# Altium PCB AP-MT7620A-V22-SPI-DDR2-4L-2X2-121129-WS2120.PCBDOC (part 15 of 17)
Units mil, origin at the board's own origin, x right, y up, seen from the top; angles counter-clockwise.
Board outline 7316 x 4279 mil, 4 copper layers (Top, Inner Layer 2, Inner Layer 3, Bottom), stack 35.4 mil thick; 640 components, 473 nets, 2041 pads, 2358 vias.
Unrouted connection lines stored in the file: 11.
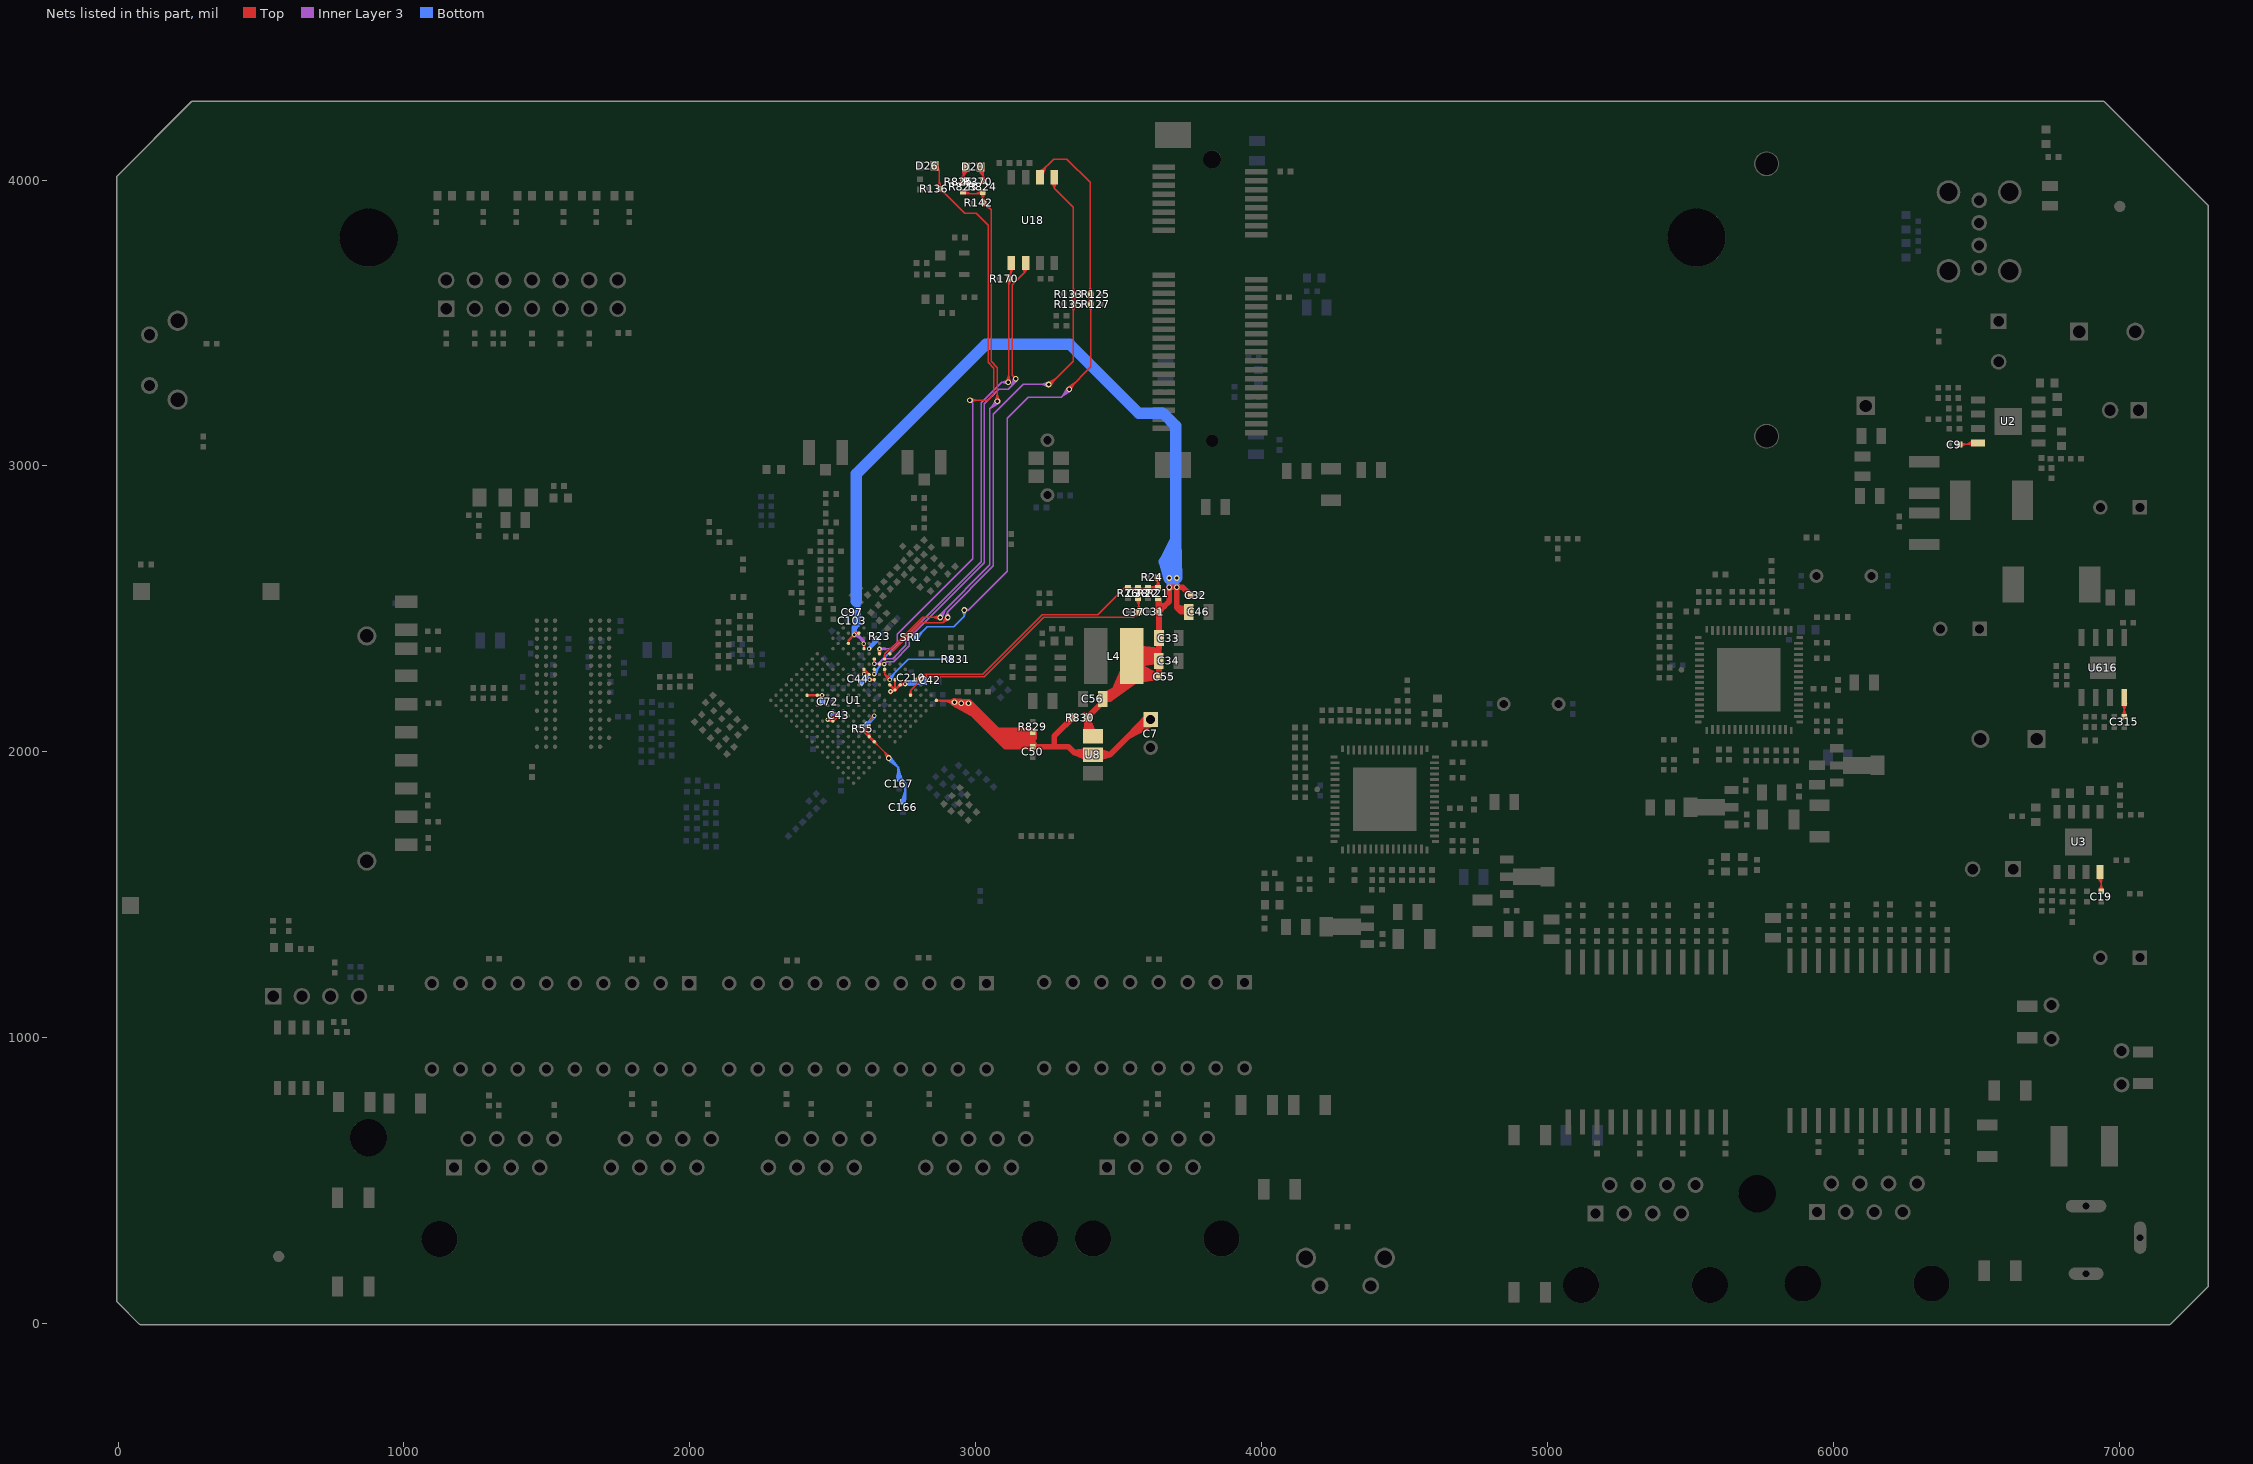
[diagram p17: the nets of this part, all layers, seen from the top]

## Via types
v1: diameter 20, hole 12, Top to Bottom, 2117 vias
v2: diameter 16, hole 8, Top to Bottom, 241 vias

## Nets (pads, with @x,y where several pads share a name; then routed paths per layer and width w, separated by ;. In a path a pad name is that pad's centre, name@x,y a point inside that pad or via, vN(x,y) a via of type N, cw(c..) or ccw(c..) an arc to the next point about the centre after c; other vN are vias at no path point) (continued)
SECLED_6-LED1: D20.1 R370.1 R824.2 | length 1100.5
  Top w4: R824.2@3025,3994 3026,3994 R370.1@3027,3994
  Top w4.5: D20.1@3006.28,4038.36 3026,4014.57 ; D20.1@3009.99,4041 3026,4014.57 ; D20.1@3014.01,4043.05 3026,4014.57 ; D20.1@3016.59,4044 3026,4014.57 ; D20.1@3016.59,4046 3022.59,4040 3026,4040 R370.1@3026,3994 ; R370.1@3017.42,3995.6 3026,4017.53 ; D20.1@3019.25,4044.72 3026,4014.57 ; R370.1@3021.77,3994.36 3026,4017.53 ; D20.1@3023.71,4045.38 3026,4014.57 ; R824.2@3025,3994 3026,4017.53 ; R370.1@3028.25,3994.09 3026,4017.53 ; D20.1@3028.26,4045.38 3026,4014.57 ; R370.1@3032.69,3994.95 3026,4017.53 ; R370.1@3019.31,3994.95 3026,4017.53 ; R370.1@3019.31,3994.95 3026,4017.53 ; R370.1@3019.31,3994.95 3026,4017.53 ; R370.1@3019.31,3994.95 3026,4017.53 ; R370.1@3019.31,3994.95 3026,4017.53 ; R370.1@3019.31,3994.95 3026,4017.53 ; R370.1@3023.75,3994.09 3026,4017.53 ; R370.1@3023.75,3994.09 3026,4017.53 ; R370.1@3023.75,3994.09 3026,4017.53 ; R370.1@3023.75,3994.09 3026,4017.53 ; R370.1@3023.75,3994.09 3026,4017.53 ; R370.1@3023.75,3994.09 3026,4017.53 ; 3026,4017.53 R370.1@3034.58,3995.6 ; 3026,4017.53 R370.1@3030.23,3994.36 ; 3026,4017.53 R370.1@3027,3994 ; 3026,4017.53 R370.1@3034.58,3995.6 ; 3026,4017.53 R370.1@3030.23,3994.36 ; 3026,4017.53 R370.1@3027,3994 ; 3026,4017.53 R370.1@3034.58,3995.6 ; 3026,4017.53 R370.1@3030.23,3994.36 ; 3026,4017.53 R370.1@3027,3994 ; 3026,4017.53 R370.1@3034.58,3995.6 ; 3026,4017.53 R370.1@3030.23,3994.36 ; 3026,4017.53 R370.1@3027,3994 ; 3026,4017.53 R370.1@3034.58,3995.6 ; 3026,4017.53 R370.1@3030.23,3994.36 ; 3026,4017.53 R370.1@3027,3994 ; 3026,4017.53 R370.1@3034.58,3995.6 ; 3026,4017.53 R370.1@3030.23,3994.36 ; 3026,4017.53 R370.1@3027,3994
SECU_LED_6-LED1: D20.2 R823.2 R825.1 | length 1077
  Top w4: R823.2@2956,3995 R825.1@2958,3995
  Top w4.5: R823.2@2948.36,3996.28 2956,4018.5 ; R823.2@2950.27,3995.62 2956,4018.63 ; D20.2@2953.75,4045.42 2956,4015.25 ; R823.2@2954.75,3994.95 2956,4018.63 ; R825.1@2958,3995 2956,4018.63 ; D20.2@2958.3,4045.41 2956,4015.25 ; R823.2@2961.21,3995.5 2956,4018.63 ; D20.2@2962.76,4044.74 2956,4015.25 ; D20.2@2965.41,4044 2956,4015.25 ; D20.2@2965.41,4046 2956,4046 R823.2@2956,3995 ; R823.2@2965.51,3996.91 2956,4018.63 ; D20.2@2967.98,4043.03 2956,4015.25 ; D20.2@2971.98,4040.94 2956,4015.25 ; D20.2@2975.65,4038.25 2956,4015.25 ; R823.2@2948.35,3996.27 2956,4018.63 ; R823.2@2948.35,3996.27 2956,4018.63 ; R823.2@2948.36,3996.27 2956,4018.54 ; R823.2@2948.35,3996.27 2956,4018.63 ; R823.2@2948.35,3996.27 2956,4018.61 ; R823.2@2952.76,3995.22 2956,4018.63 ; R823.2@2952.76,3995.22 2956,4018.63 ; R823.2@2952.76,3995.22 2956,4018.54 ; R823.2@2952.76,3995.22 2956,4018.63 ; R823.2@2952.76,3995.22 2956,4018.61 ; R823.2@2952.76,3995.22 2956,4018.5 ; R823.2@2956,3995 2956,4018.63 ; R823.2@2956,3995 2956,4018.63 ; R823.2@2956,3995 2956,4018.54 ; R823.2@2956,3995 2956,4018.63 ; R823.2@2956,3995 2956,4018.61 ; 2956,4018.5 2963.64,3996.28 2956,4018.54 ; 2956,4018.5 R823.2@2959.24,3995.22 ; 2956,4018.54 R823.2@2959.24,3995.23 ; 2956,4018.61 R823.2@2963.65,3996.27 ; 2956,4018.61 R823.2@2959.24,3995.22 ; 2956,4018.63 R823.2@2963.65,3996.27 ; 2956,4018.63 R823.2@2959.24,3995.22 ; 2956,4018.63 R823.2@2963.65,3996.27 ; 2956,4018.63 R823.2@2959.24,3995.22 ; 2956,4018.63 R823.2@2963.65,3996.27 ; 2956,4018.63 R823.2@2959.24,3995.22
SFLASH_CLK_1-CPU-RT0: SR1.1 U1.D8 | length 383.6
  Top w8: v2(2645.2,2272) U1.D8@2645.38,2288.57 v2(2645.2,2272)
  Bottom w5: v2@2640.91,2275.45 2660.89,2295.89 ; v2@2650.07,2269.44 2660.89,2295.89 ; SR1.1@2750.61,2405.21 2733.05,2381.67 ; SR1.1@2759.89,2393.59 2733.05,2381.67 ; 2660.89,2295.89 v2(2645.2,2272) 2645.2,2280.2 2664,2299 2664,2312.62 2751.38,2400 SR1.1@2756,2400 2733.05,2381.67
SOC_1.2VD: C7.1 C42.1 C43.1 C44.1 C50.1 C72.1 C166.1 C167.1 C210.1 R23.1 R55.1 R829.1 R830.1 U1.A17 U1.C11 U1.C12 U1.D11 U1.D12 U1.E7 U1.E8 U1.E9 U1.K13 U1.L13 U1.L14 U1.L15 U1.M5 U1.M9 U1.N4 U1.N9 U8.2 | length 9993
  Top w4: U1.L14@2624.84,2050.29 2639.95,2040.67 ; U1.K13@2627.29,2089.52 U1.K13@2628,2090.24 ; U1.L14@2630.33,2055.78 2639.95,2040.67 ; 2631,2110.47 2631,2111.17 ; v2@2640.44,2129.32 2631,2111.17 ; U1.L15@2642.05,2033.19 2634.28,2049.58 ; U1.L15@2642.67,2032.42 2630.98,2046.38 ; U1.L15@2642.94,2032.19 2658.04,2022.58 U1.L15@2648.43,2037.68 ; U1.L15@2647.43,2038.57 2630.98,2046.38 ; U1.L15@2648.19,2037.95 2634.28,2049.58 ; v2@2648.93,2121.02 2631,2111.17 ; v1@2689.05,1974.42 2679.05,2001.57 ; v1@2692.71,1976.07 2679.05,2001.57 ; U1.D11@2697.22,2231.24 2712.33,2221.62 ; v1@2699.16,1980.78 2679.05,2001.57 ; v1@2701.85,1983.76 2679.05,2001.57 ; U1.D11@2702.71,2236.73 2712.33,2221.62 ; U1.D12@2714.43,2214.15 2706.66,2230.53 ; U1.D12@2714.95,2218.9 2728.88,2230.55 ; U1.D12@2715.05,2213.38 2703.37,2227.33 ; U1.D12@2715.72,2219.52 2732.12,2227.31 ; U1.D12@2719.81,2219.52 2703.37,2227.33 ; U1.D12@2720.47,2213.38 2732.12,2227.31 ; U1.D12@2720.57,2218.9 2706.66,2230.53 ; U1.D12@2721.09,2214.15 2728.88,2230.55 ; U1.C12@2732.81,2236.73 2723.2,2221.62 ; U1.C12@2734.56,2237.97 2741,2238.17 ; U1.C12@2738.3,2231.24 2723.2,2221.62 ; U1.C12@2739.05,2232.03 2741,2238.17 ; U1.A17@2862.52,2180 U1.A17@2866,2180 ; 2630.98,2046.38 U1.L15@2645.38,2035.24 ; 2631,2111.17 2643.83,2124 2643.83,2124.33 v2(2645.3,2125.8) 2631,2111.17 ; 2632.72,2047.9 2642.33,2032.79 2632.72,2047.9 ; 2632.72,2047.9 2647.83,2038.28 2632.72,2047.9 ; 2634.28,2049.58 U1.L15@2645.38,2035.24 ; 2639.95,2040.67 U1.L14@2627.29,2053.33 U1.L15@2645.38,2035.24 ; 2639.95,2040.67 U1.L15@2642.01,2033.27 ; 2639.95,2040.67 U1.L15@2647.35,2038.61 ; 2639.95,2040.67 U1.L15@2645.38,2035.24 ; 2639.95,2040.67 U1.L15@2642.01,2033.27 ; 2639.95,2040.67 U1.L15@2647.35,2038.61 ; 2639.95,2040.67 U1.L15@2642.01,2033.27 ; 2639.95,2040.67 U1.L15@2647.35,2038.61 ; 2639.95,2040.67 U1.L15@2645.38,2035.24 ; U1.L15@2645.38,2035.24 2695.8,1984.82 v1(2696.1,1978.2) 2679.05,2001.57 ; 2703.37,2227.33 U1.D12@2717.76,2216.19 ; 2705.1,2228.85 2714.72,2213.75 2705.1,2228.85 ; 2705.1,2228.85 2720.21,2219.24 2705.1,2228.85 ; 2705.1,2228.85 U1.D12@2717.76,2216.19 ; 2705.1,2228.85 U1.D12@2717.76,2216.19 ; 2706.66,2230.53 U1.D12@2717.76,2216.19 ; 2712.33,2221.62 U1.D11@2699.67,2234.29 2715.98,2217.98 U1.D12@2717.76,2216.19 ; 2712.33,2221.62 U1.D12@2714.39,2214.22 ; 2712.33,2221.62 U1.D12@2719.73,2219.56 ; 2712.33,2221.62 U1.D12@2717.76,2216.19 ; 2712.33,2221.62 U1.D12@2714.39,2214.22 ; 2712.33,2221.62 U1.D12@2719.73,2219.56 ; 2712.33,2221.62 U1.D12@2717.76,2216.19 ; 2712.33,2221.62 U1.D12@2714.39,2214.22 ; 2712.33,2221.62 U1.D12@2719.73,2219.56 ; 2712.33,2221.62 U1.D12@2717.76,2216.19 ; U1.D12@2715.79,2219.56 2723.2,2221.62 ; U1.D12@2715.79,2219.56 2723.2,2221.62 ; U1.D12@2715.79,2219.56 2723.2,2221.62 ; U1.D12@2717.76,2216.19 U1.C12@2735.86,2234.29 ; U1.D12@2717.76,2216.19 2730.42,2228.85 ; U1.D12@2717.76,2216.19 2732.12,2227.31 ; U1.D12@2717.76,2216.19 2723.2,2221.62 ; U1.D12@2717.76,2216.19 2728.88,2230.55 ; U1.D12@2717.76,2216.19 2723.2,2221.62 ; U1.D12@2717.76,2216.19 2730.42,2228.85 ; U1.D12@2717.76,2216.19 2723.2,2221.62 ; U1.D12@2721.13,2214.22 2723.2,2221.62 ; U1.D12@2721.13,2214.22 2723.2,2221.62 ; U1.D12@2721.13,2214.22 2723.2,2221.62 ; 2723.2,2221.62 U1.C12@2735.86,2234.29 ; 2730.42,2228.85 2715.32,2219.24 2730.42,2228.85 ; 2730.42,2228.85 2720.81,2213.75 2730.42,2228.85 ; U1.C12@2735.86,2234.29 2739.74,2238.17 2741,2238.17 ; U1.C12@2735.86,2234.29 2741,2238.17
  Top w8: U1.N4@2413.98,2198.1 U1.M5@2446.33,2198.1 ; U1.E7@2609.19,2288.57 U1.E7@2610.38,2287.38 ; U1.E8@2626.88,2270.88 U1.E8@2627.29,2270.48 ; U1.D12@2717.76,2220.03 U1.C11@2717.76,2252.38 U1.D12@2717.76,2216.19 ; U1.A17@2861,2179.5 2965.5,2179.5 ; U1.A17@2862.52,2180 2894.85,2179.5 ; v1@2924.37,2167.37 2888.78,2179.5 ; v1@2924.33,2167.38 v1@2948.13,2164.3 ; v1@2925.31,2179.16 2962.62,2179.5 ; v1@2925.43,2167.2 2964.5,2167.55 ; v1@2925.73,2179.18 2964.22,2176.9 ; v1@2925.91,2179.18 v1@2950.99,2175.92 ; v1@2926.17,2167.19 2964.64,2172.32 ; v1@2926.38,2179.16 2888.78,2179.5 ; v1@2926.44,2179.15 2964.64,2172.32 ; v1@2926.88,2167.27 2964.22,2176.9 ; v1@2927.19,2167.34 v1@2950.99,2175.92 ; v1@2927.33,2167.37 2962.62,2179.5 ; v1@2947.75,2175.56 2965.5,2179.5 ; v1@2949.3,2164.04 v1@2973.29,2164.25 ; v1@2949.33,2175.96 v1@2975.91,2175.93 ; v1@2950.72,2164.04 v1(2975,2170) ; v1@2950.72,2175.96 v1(2975,2170) ; v1@2951.99,2164.34 v1@2975.91,2175.93 ; v1@2952.16,2175.6 v1@2973.29,2164.25 ; v1@2953.94,2165.47 2965.5,2179.5 ; U1.N4@2410.14,2198.1 U1.M5@2446.33,2198.1 ; U1.N4@2410.14,2198.1 2442.49,2198.1 U1.N4@2410.14,2198.1 ; U1.M5@2446.33,2198.1 v2(2462.4,2198.1) U1.M5@2446.33,2198.1 ; v2(2482,2113) 2483,2112 v2@2483,2107.62 ; v2(2482,2113) U1.N9@2500.62,2107.62 ; v2(2482,2113) U1.N9@2500.62,2107.62 ; v2@2483,2107.62 U1.N9@2500.62,2107.62 ; v2@2483,2107.62 U1.N9@2500.62,2107.62 ; U1.L13@2609.19,2071.43 2609.33,2071.29 2619,2071.29 ; U1.L13@2609.19,2071.43 2610,2080.52 ; U1.L13@2609.19,2071.43 2619,2089.52 ; U1.L13@2609.19,2071.43 2610,2080.52 ; U1.L13@2609.19,2071.43 2619,2071.29 ; U1.L13@2609.19,2071.43 2627.29,2063 ; U1.L13@2609.19,2071.43 2619,2071.29 ; U1.L13@2609.19,2071.43 2619,2071.29 ; U1.L13@2609.19,2071.43 U1.K13@2627.29,2089.52 ; U1.L13@2609.19,2071.43 2610,2080.52 ; U1.L13@2609.19,2071.43 U1.L14@2627.29,2053.33 ; 2610,2080.52 2619,2089.52 ; 2610,2080.52 2610,2071.29 2619,2071.29 ; 2610,2080.52 U1.K13@2627.29,2089.52 ; 2619,2071.29 2627.29,2063 ; 2619,2071.29 U1.L14@2627.29,2053.33 ; 2619,2089.52 U1.K13@2627.29,2089.52 ; U1.L14@2627.29,2053.33 2627.29,2063 ; U1.L14@2627.29,2053.33 2627.29,2063 ; U1.L14@2627.29,2053.33 2627.29,2063 ; U1.L14@2627.29,2053.33 2627.29,2063 ; v2(2628.8,2252.4) U1.E9@2645.38,2252.38 ; v2(2628.8,2252.4) U1.E9@2645.38,2252.38 ; v2(2628.8,2252.4) U1.E9@2645.38,2252.38 ; v2(2628.8,2252.4) U1.E9@2645.38,2252.38 ; v2@2702,2205 2715.98,2217.98 v2(2702,2211) ; v2@2702,2205 v2(2702,2211) ; v2@2702,2205 U1.D12@2717.76,2216.19 ; v2(2702,2211) U1.D12@2717.76,2216.19 ; U1.D12@2717.76,2216.19 2717.76,2248.54 U1.D12@2717.76,2216.19 ; 2888.78,2179.5 v1(2925.84,2173.18) ; 2911.46,2179.5 v1@2948.13,2164.3 ; 2911.46,2179.5 v1@2950.99,2175.92 ; 2911.46,2179.5 v1(2950,2170) ; 2911.46,2179.5 v1@2922.43,2168.25 ; 2911.46,2179.5 v1@2927.16,2179.04 ; 2911.46,2179.5 v1(2925.84,2173.18) ; 2911.46,2179.5 v1@2922.43,2168.25 ; 2911.46,2179.5 v1@2927.16,2179.04 ; 2911.46,2179.5 v1(2925.84,2173.18) ; 2911.46,2179.5 v1@2922.43,2168.25 ; 2911.46,2179.5 v1@2927.16,2179.04 ; 2911.46,2179.5 v1(2925.84,2173.18) ; v1@2924.46,2167.35 v1@2946.36,2165.23 ; v1@2924.46,2167.35 v1@2946.36,2165.23 ; v1@2924.46,2167.35 v1@2946.36,2165.23 ; v1@2925.8,2167.18 v1(2950,2170) ; v1@2925.8,2167.18 v1(2950,2170) ; v1@2925.8,2167.18 v1(2950,2170) ; v1@2925.8,2167.18 v1(2950,2170) ; v1(2925.84,2173.18) 2962.62,2179.5 ; v1(2925.84,2173.18) 2964.5,2167.55 ; v1(2925.84,2173.18) 2964.22,2176.9 ; v1(2925.84,2173.18) 2964.64,2172.32 ; v1(2925.84,2173.18) v1@2948.13,2164.3 ; v1(2925.84,2173.18) v1@2950.99,2175.92 ; v1(2925.84,2173.18) v1(2950,2170) ; v1(2925.84,2173.18) v1@2946.36,2165.23 ; v1(2925.84,2173.18) v1@2952.05,2175.64 ; v1(2925.84,2173.18) v1(2950,2170) ; v1(2925.84,2173.18) v1@2946.36,2165.23 ; v1(2925.84,2173.18) v1@2952.05,2175.64 ; v1(2925.84,2173.18) v1(2950,2170) ; v1(2925.84,2173.18) v1@2946.36,2165.23 ; v1(2925.84,2173.18) v1@2952.05,2175.64 ; v1(2925.84,2173.18) v1(2950,2170) ; v1@2925.97,2179.18 v1@2952.05,2175.64 ; v1@2925.97,2179.18 v1@2952.05,2175.64 ; v1@2925.97,2179.18 v1@2952.05,2175.64 ; v1@2927.08,2167.31 v1@2952.05,2175.64 ; v1@2927.08,2167.31 v1@2952.05,2175.64 ; v1@2927.08,2167.31 v1@2952.05,2175.64 ; v1@2927.16,2179.04 2964.5,2167.55 ; v1@2927.35,2178.99 v1(2950,2170) ; v1@2927.35,2178.99 v1(2950,2170) ; v1@2927.35,2178.99 v1(2950,2170) ; v1@2927.35,2178.99 v1(2950,2170) ; v1@2928.74,2178.44 v1@2948.13,2164.3 ; v1@2928.75,2178.43 v1@2946.36,2165.23 ; v1@2928.75,2178.43 v1@2946.36,2165.23 ; v1@2928.75,2178.43 v1@2946.36,2165.23 ; v1@2932.64,2179.5 v1@2973.29,2164.25 ; v1@2932.64,2179.5 v1@2975.91,2175.93 ; v1@2932.64,2179.5 v1(2975,2170) ; v1@2932.64,2179.5 v1@2946.36,2165.23 ; v1@2932.64,2179.5 v1@2952.05,2175.64 ; v1@2932.64,2179.5 v1(2950,2170) ; v1@2932.64,2179.5 v1@2946.36,2165.23 ; v1@2932.64,2179.5 v1@2952.05,2175.64 ; v1@2932.64,2179.5 v1(2950,2170) ; v1@2932.64,2179.5 v1@2946.36,2165.23 ; v1@2932.64,2179.5 v1@2952.05,2175.64 ; v1@2932.64,2179.5 v1(2950,2170) ; v1(2950,2170) 2965.5,2179.5 ; v1(2950,2170) v1@2973.29,2164.25 ; v1(2950,2170) v1@2975.91,2175.93 ; v1(2950,2170) v1(2975,2170) ; 2965.5,2179.5 v1(2975,2170)
  Top w10: 2500.62,2125.68 2500.62,2114.2 ; U1.E7@2610.38,2287.38 U1.E7@2610,2287 ; U1.E8@2626.88,2270.88 U1.E8@2626.76,2271 ; U1.N9@2500.62,2107.62 2500.62,2114.2 ; U1.N9@2500.62,2107.62 2512.13,2125.71 ; U1.N9@2500.62,2107.62 U1.M9@2518.71,2125.71 ; 2500.62,2114.2 2512.13,2125.71 ; 2500.62,2114.2 U1.M9@2518.71,2125.71 ; 2512.13,2125.71 2500.65,2125.71 U1.M9@2518.71,2125.71 ; 2512.13,2125.71 U1.M9@2518.71,2125.71 ; U1.E7@2609.19,2288.57 2610,2281 ; U1.E7@2609.19,2288.57 2610,2281 ; U1.E7@2609.19,2288.57 v2(2610,2271) ; U1.E7@2609.19,2288.57 2620,2271 ; U1.E7@2609.19,2288.57 2610,2281 ; U1.E7@2609.19,2288.57 U1.E8@2627.29,2270.48 ; U1.E7@2609.19,2288.57 v2(2610,2271) ; U1.E7@2609.19,2288.57 v2(2610,2271) ; U1.E7@2609.19,2288.57 v2(2610,2271) ; U1.E7@2609.19,2288.57 v2(2610,2271) ; U1.E7@2609.19,2288.57 v2(2610,2271) ; U1.E7@2609.19,2288.57 v2(2610,2271) ; v2(2610,2271) 2610,2281 ; v2(2610,2271) 2620,2271 ; v2(2610,2271) U1.E8@2627.29,2270.48 ; v2(2610,2271) U1.E7@2610,2287 ; v2(2610,2271) U1.E8@2626.76,2271 ; v2(2610,2271) U1.E8@2627.29,2270.48 ; v2(2610,2271) U1.E8@2627.29,2270.48 ; 2610,2281 U1.E7@2610,2287 ; 2610,2281 2620,2271 ; 2610,2281 U1.E8@2627.29,2270.48 ; 2620,2271 U1.E8@2626.76,2271 ; U1.C12@2735.86,2234.29 U1.C12@2738.57,2237 ; U1.C12@2735.86,2234.29 v2(2753,2237) ; U1.C12@2735.86,2234.29 v2(2753,2237) ; U1.C12@2738.57,2237 v2(2753,2237) ; U1.C12@2738.57,2237 v2(2753,2237)
  Top w20: 3005.39,2116.61 v1(2950,2170) ; 3028.03,2093.97 v1(2975,2170) ; 3130,2018 C50.1@3200,2018 ; R829.1@3200,2061.41 3200,2050 ; 3282.98,2063.57 R830.1@3339.41,2118 ; R830.1@3339.41,2120 3275,2055.59 3275,2018 C50.1@3200,2018 ; U8.2@3395.86,1975.58 3345,1998 ; U8.2@3400,1990 3345,1998 ; U8.2@3400.14,2005 3345,1998 ; U8.2@3420,1990 3470,1990 ; U8.2@3422.25,1975.17 3470,1990 ; U8.2@3422.25,2004.83 3470,1990 ; C7.1@3601.61,2124.84 3533.91,2053.91 ; C7.1@3620.41,2100.09 3533.91,2053.91 ; v1(2950,2170) v1@2952,2170 ; v1(2950,2170) v1(2975,2170) ; v1(2950,2170) v1(2975,2170) ; v1(2950,2170) v1(2975,2170) ; v1@2952,2170 3104,2018 C50.1@3200,2018 ; v1@2952,2170 v1(2975,2170) ; v1@2952,2170 v1(2975,2170) ; v1@2952,2170 v1(2975,2170) ; C50.1@3200,2018 3325,2018 3345,1998 ; C50.1@3200,2018 C50.1@3200,2026 ; C50.1@3200,2018 3200,2050 ; C50.1@3200,2018 R829.1@3200,2069 ; C50.1@3200,2026 3200,2050 ; C50.1@3200,2026 R829.1@3200,2069 ; 3200,2050 R829.1@3200,2069 ; 3200,2050 R829.1@3200,2069 ; 3345,1998 3410,1998 U8.2@3410,1990 3470,1990 ; 3470,1990 3590,2110 3608.79,2110 C7.1@3612,2113.21 3533.91,2053.91
  Top w30: 3018.74,2120.45 v1(2925.84,2173.18) ; 3039.54,2105.46 v1(2950,2170) ; 3099.73,2070 R829.1@3200,2069 ; C50.1@3200,2018 3119,2026 ; C50.1@3200,2026 3119,2026 ; R829.1@3200,2061.41 3191.41,2070 3075,2070 ; v1(2925.84,2173.18) v1(2975,2170) ; v1(2925.84,2173.18) v1(2950,2170) ; v1(2925.84,2173.18) v1(2950,2170) ; v1(2950,2170) v1(2975,2170) ; v1(2975,2170) 3075,2070 ; 3075,2070 3095,2050 ; 3095,2050 3119,2026 ; 3095,2050 3200,2050 R829.1@3200,2069 ; 3095,2050 R829.1@3200,2069
  Bottom w4: v1(2696.1,1978.2) 2696.4,1978.5 v1@2696.4,1984.3
  Bottom w8: v1@2692.18,1973.66 2725.07,1949.23 v1@2700.64,1982.12 ; v1(2696.1,1978.2) 2729,1945.3 2729,1911 C167.1@2733,1907 ; C167.1@2727,1906.83 2729,1941.69 ; C167.1@2729.77,1901.95 2754,1890 ; C167.1@2737.27,1911.22 2754,1890 ; C167.1@2738.88,1908.2 2729,1941.69 ; C166.1@2740.23,1826.64 2754,1864.06 ; C166.1@2751.95,1824.24 2754,1864.06 ; 2729,1941.69 C167.1@2733,1907 ; C167.1@2733,1907 2733,1908.22 2735.78,1908.22 2754,1890 ; C167.1@2733,1907 2754,1890 ; 2754,1864.06 C166.1@2746,1825 2754,1833 2754,1890
  Bottom w10: C44.1@2601.73,2242.77 2610,2251.04 ; C44.1@2601.73,2242.77 v2(2610,2271) ; C44.1@2601.73,2242.77 v2(2610,2271) ; 2610,2251.04 v2(2610,2271) ; 2610,2251.04 v2(2610,2271) ; v2(2462.4,2198.1) 2464,2196.5 C72.1@2464,2176 v2(2462.4,2198.1) ; v2(2482,2113) 2497,2128 C43.1@2503,2128 v2(2482,2113) ; v2(2753,2237) 2770,2237 C210.1@2775,2242 v2(2753,2237)
  Bottom w12: 2610,2251.04 2613.04,2254.09 ; R23.1@2651.27,2392.27 v2(2627.2,2361) 2653.9,2387.5 2653.9,2391.06 R23.1@2651.98,2392.98 ; v2(2610,2271) v2(2610,2271) ; v2(2610,2271) v2(2628.8,2252.4) ; v2(2610,2271) v2(2628.8,2252.4) ; v2(2610,2271) v2(2628.8,2252.4) ; v2(2610,2271) v2(2628.8,2252.4) ; 2613.04,2254.09 2628.8,2254.09 v2(2628.8,2252.4) ; 2613.04,2254.09 v2(2628.8,2252.4) ; v2(2628.8,2252.4) v2(2628.8,2252.4) ; v2@2645.3,2120.7 v2(2645.3,2125.8) ; v2@2645.3,2120.7 R55.1@2617.32,2092.72 v2(2645.3,2125.8) ; v2@2645.3,2120.7 2618.03,2093.43 v2(2645.3,2125.8)
  Bottom w15: C42.1@2815.91,2248.5 C210.1@2775,2242 2810.5,2242 2815.91,2247.41 C42.1@2815.91,2250.5
SOC_1.5VD: C31.1 C32.1 C33.1 C34.1 C46.1 C55.1 C56.1 C97.1 C103.1 L4.2 R21.1 R830.2 U1.B3 U1.C5 U1.D3 U8.3 | length 14020.3
  Top w4: v2(2609,2378.3) v2@2609.19,2378.11 ; R830.2@3379.08,2118.62 3379.5,2138.5 ; R830.2@3383.19,2118.96 3379.5,2138.5 ; R830.2@3387.06,2120.11 3379.5,2138.5 ; R830.2@3390.59,2120 3389.59,2121 3379.5,2121 3379.5,2138.5 ; R830.2@3390.59,2122 3379.5,2138.5 ; R830.2@3393.67,2124.55 3379.5,2138.5 ; R830.2@3396.2,2127.71 3379.5,2138.5 ; R830.2@3398.07,2131.39 3379.5,2138.5
  Top w8: U1.D3@2554.9,2379.05 2554.9,2389.9 ; v2(2609,2378.3) U1.C5@2609.19,2360.95 v2@2609.19,2378.11 ; 2554.9,2389.9 v2(2575,2410) ; 2554.9,2389.9 v2(2575,2410) ; v2(2575,2410) 2575,2411.24 v2@2579,2415.24 ; v2(2575,2410) U1.B3@2591.1,2415.24 ; v2(2575,2410) U1.B3@2591.1,2415.24 ; v2@2579,2415.24 U1.B3@2591.1,2415.24 ; v2@2579,2415.24 U1.B3@2591.1,2415.24
  Top w20: U8.3@3410,2055 3395,2070 U8.3@3390.59,2070 ; 3517.85,2232.85 3444.45,2196 3517.96,2232.96 ; L4.2@3519.16,2294.11 3474.02,2189.02 ; L4.2@3519.2,2294.16 3473.37,2188.37 ; L4.2@3544.56,2366.31 3640.55,2355 ; L4.2@3544.78,2266.64 C55.1@3641,2262 ; L4.2@3545.91,2246.57 C55.1@3641,2262 ; L4.2@3545.99,2270 3545.99,2260.99 L4.2@3543.5,2258.5 ; L4.2@3545.99,2316 L4.2@3545.99,2335 ; L4.2@3548.05,2365.9 C34.1@3640.55,2329 ; L4.2@3548.52,2288.97 C55.1@3641,2262 ; L4.2@3556.13,2307.57 C55.1@3641,2262 ; L4.2@3571,2262 C55.1@3641,2262 ; L4.2@3571.07,2265.37 C55.1@3641,2262 ; L4.2@3571.77,2250.77 C55.1@3641,2262 ; L4.2@3571.82,2273.59 C55.1@3641,2262 ; L4.2@3573.4,2281.71 C55.1@3641,2262 ; L4.2@3578.14,2295.75 C55.1@3641,2262 ; R21.1@3638,2538 3641,2535 3641,2510 ; C34.1@3640.55,2307 C55.1@3641,2262 ; C31.1@3641,2486 C33.1@3641.55,2409 ; C33.1@3641.47,2420 C31.1@3641,2490 ; C33.1@3641.55,2398 C33.1@3640.55,2397 ; C46.1@3745.55,2501 3703,2505.55 ; C32.1@3752,2548 3724,2576 v1(3703,2576) ; U8.3@3390.59,2070 R830.2@3390.59,2120 ; U8.3@3390.59,2070 R830.2@3390.59,2118 ; R830.2@3390.59,2118 3385.01,2054.56 R830.2@3390.59,2120 ; R830.2@3390.59,2118 3400,2055 R830.2@3390.59,2120 ; R830.2@3390.59,2118 3414.5,2058.83 R830.2@3390.59,2120 ; R830.2@3390.59,2120 C56.1@3440,2169.41 ; R830.2@3390.59,2120 3444.45,2174 3390.59,2122 C56.1@3440,2169.41 ; C56.1@3440,2169.41 3440,2180.55 C56.1@3444.45,2185 ; C56.1@3444.45,2185 3470,2185 ; C56.1@3444.45,2185 3470,2185 ; C56.1@3444.45,2185 3470,2185 ; 3470,2185 L4.2@3547,2262 ; 3470,2185 L4.2@3543.5,2258.5 ; 3473.37,2188.37 3567.42,2255.05 3474.02,2189.02 ; 3473.37,2188.37 3554.44,2270.35 3474.02,2189.02 ; 3473.37,2188.37 3536.85,2284.61 3474.02,2189.02 ; 3473.37,2188.37 L4.2@3545.99,2277.91 ; 3474.02,2189.02 L4.2@3545.99,2277.91 ; L4.2@3543.5,2258.5 L4.2@3547,2262 ; L4.2@3545.99,2277.91 C55.1@3641,2262 ; L4.2@3545.99,2335 3640.55,2355 ; L4.2@3545.99,2335 C34.1@3640.55,2318 ; L4.2@3547,2262 C55.1@3641,2262 ; C34.1@3640.55,2318 3640.55,2355 ; C34.1@3640.55,2318 3641,2317.55 C55.1@3641,2262 ; C34.1@3640.55,2318 3557.36,2305.8 3640.55,2355 ; C34.1@3640.55,2318 3544.3,2346.21 3640.55,2355 ; C34.1@3640.55,2318 3548.99,2324.06 3640.55,2355 ; C34.1@3640.55,2329 C33.1@3640.55,2397 ; C34.1@3640.55,2329 3640.55,2355 ; C34.1@3640.55,2329 C33.1@3640.55,2390 ; C34.1@3640.55,2329 3640.55,2355 ; C34.1@3640.55,2329 3640.55,2355 ; C34.1@3640.55,2329 3640.55,2355 ; C34.1@3640.55,2329 3545.99,2355 3640.55,2355 ; C34.1@3640.55,2329 3640.55,2355 ; C34.1@3640.55,2329 3640.55,2355 ; C34.1@3640.55,2329 3640.55,2355 ; C34.1@3640.55,2329 3640.55,2355 ; C34.1@3640.55,2329 3640.55,2355 ; C34.1@3640.55,2329 C33.1@3641.55,2387 ; C34.1@3640.55,2329 C33.1@3641.55,2387 ; 3640.55,2355 C33.1@3640.55,2397 ; 3640.55,2355 C33.1@3640.55,2390 ; 3640.55,2355 C33.1@3641.55,2387 ; 3640.55,2355 C33.1@3641.55,2387 ; C33.1@3640.55,2390 3641,2390.45 C31.1@3641,2490 ; C31.1@3641,2490 3641,2510 ; C31.1@3641,2490 3641,2510 ; C31.1@3641,2490 R21.1@3638,2537 3641,2510 ; C31.1@3641,2490 3661,2510 ; C31.1@3641,2490 3641,2510 ; 3641,2510 3661,2510 ; 3661,2510 3677,2526 v1(3677,2575) ; v1(3677,2575) v1@3677,2575.5 ; v1(3677,2575) v1@3703,2575.5 ; v1(3677,2575) v1(3703,2576) ; v1@3677,2575.5 v1@3703,2575.5 ; v1@3677,2575.5 v1(3703,2576) ; 3703,2505.55 v1@3703,2575.5 ; 3703,2505.55 3718.55,2490 ; 3703,2505.55 v1(3703,2576) ; v1@3703,2575.5 v1(3703,2576) ; 3718.55,2490 C46.1@3745.55,2490 3718.55,2490
  Top w30: L4.2@3545.99,2270 L4.2@3545.99,2316 ; L4.2@3545.99,2335 L4.2@3545.99,2355
  Inner Layer 3 w8: v2@2577.1,2410.2 2586.8,2410.2 ; 2587.1,2409.9 v2(2609,2378.3) 2609,2388 2586.8,2410.2 ; 2606.82,2390.18 v2(2575,2410) ; v2(2575,2410) 2586.8,2410.2 ; v2(2575,2410) 2586.8,2410.2
  Inner Layer 3 w10: v2(2575,2410) 2575.2,2410.2 v2@2577.1,2410.2
  Bottom w4: v1@3669.01,2574.56 3671.66,2599.33 ; v1@3669.01,2575.48 v1@3674.45,2599.13 ; v1@3669.11,2606.67 v1@3677,2584 ; v1@3669.29,2577.14 v1@3679.55,2599.13 ; v1@3669.56,2577.95 3682.34,2599.33 ; v1@3673,2574.91 v1@3674.45,2599.13 ; v1@3673.01,2607.67 v1@3677,2584 ; v1@3673.04,2574.46 3671.66,2599.33 ; v1@3673.07,2575.75 v1@3679.55,2599.13 ; v1@3673.17,2576.17 3682.34,2599.33 ; v1@3675.53,2582.86 v1@3700.29,2583.41 ; v1@3675.84,2600.08 v1@3700.45,2600.54 ; v1@3675.84,2615.92 v1@3700.45,2615.46 ; v1@3675.95,2578.86 v1@3700.29,2583.41 ; v1@3676.1,2604.1 v1@3700.45,2600.54 ; v1@3676.1,2611.9 v1@3700.45,2615.46 ; v1@3676.16,2567.04 v1@3700.6,2568.49 ; v1@3676.25,2571.07 v1@3700.6,2568.49 ; v1@3676.56,2578.98 v1@3700.78,2579.64 ; v1@3676.72,2604.01 v1@3700.86,2604.32 ; v1@3676.72,2611.99 v1@3700.86,2611.68 ; v1@3676.79,2583 v1@3700.78,2579.64 ; v1@3676.88,2571 v1@3700.94,2572.27 ; v1@3677.11,2600 v1@3700.86,2604.32 ; v1@3677.11,2616 v1@3700.86,2611.68 ; v1@3677.17,2579 v1@3701,2575.96 ; v1@3677.25,2578.99 v1@3701,2575.5 ; v1@3677.42,2571.02 v1@3701,2575.5 ; v1@3677.43,2567.01 v1@3700.94,2572.27 ; v1@3677.49,2571.03 v1@3701,2575.96 ; v1@3677.78,2578.92 v1@3700.94,2572.27 ; v1@3677.94,2604.11 v1@3700.86,2611.68 ; v1@3677.94,2611.89 v1@3700.86,2604.32 ; v1@3678.02,2582.94 v1@3701,2575.96 ; v1@3678.09,2571.15 v1@3700.78,2579.64 ; v1@3678.17,2582.91 v1@3701,2575.5 ; v1@3678.38,2578.76 v1@3700.6,2568.49 ; v1@3678.5,2567.14 v1@3701,2575.5 ; v1@3678.52,2604.3 v1@3700.45,2615.46 ; v1@3678.52,2611.7 v1@3700.45,2600.54 ; v1@3678.65,2567.17 v1@3701,2575.96 ; v1@3678.66,2571.36 v1@3700.29,2583.41 ; v1@3679.21,2582.69 v1@3700.94,2572.27 ; v1@3679.51,2600.4 v1@3700.86,2611.68 ; v1@3679.51,2615.6 v1@3700.86,2604.32 ; v1@3679.81,2567.51 v1@3700.78,2579.64 ; v1@3680.36,2582.26 v1@3700.6,2568.49 ; v1@3680.63,2600.87 v1@3700.45,2615.46 ; v1@3680.63,2615.13 v1@3700.45,2600.54 ; v1@3680.83,2576.17 3671.66,2599.33 ; v1@3680.9,2568.01 v1@3700.29,2583.41 ; v1@3680.96,2574.46 3682.34,2599.33 ; v1@3680.93,2575.75 v1@3674.45,2599.13 ; v1@3681,2574.91 v1@3679.55,2599.13 ; v1@3680.99,2607.67 v1@3677,2584 ; v1@3684.44,2577.95 3671.66,2599.33 ; v1@3684.71,2577.14 v1@3674.45,2599.13 ; v1@3684.89,2606.67 v1@3677,2584 ; v1@3684.99,2574.56 3682.34,2599.33 ; v1@3684.99,2575.48 v1@3679.55,2599.13 ; v1@3701.5,2583.86 v1@3679,2575.5 ; v1@3701.67,2600.11 v1@3679,2608 ; v1@3701.67,2615.89 v1@3679,2608 ; v1@3701.83,2568.09 v1@3679,2575.5 ; v1@3702.58,2579.98 v1@3679,2575.5 ; v1@3702.67,2604.01 v1@3679,2608 ; v1@3702.67,2611.99 v1@3679,2608 ; v1@3702.75,2572.01 v1@3679,2575.5 ; 3671.66,2599.33 v1(3677,2575) ; v1@3674.45,2599.13 v1(3677,2575) ; v1(3677,2575) v1@3677,2575.5 ; v1(3677,2575) v1@3701,2575.5 ; v1(3677,2575) v1@3700.6,2568.49 ; v1(3677,2575) v1@3700.94,2572.27 ; v1(3677,2575) v1@3700.78,2579.64 ; v1(3677,2575) v1@3701,2575.96 ; v1(3677,2575) v1@3677,2599 ; v1(3677,2575) v1@3700.29,2583.41 ; v1(3677,2575) 3682.34,2599.33 ; v1(3677,2575) v1@3679.55,2599.13 ; v1(3677,2575) v1@3677,2599 ; v1@3677,2575.5 3677,2577 v1(3677,2608) ; v1@3677,2575.5 3703,2575.5 v1(3703,2576) v1@3679,2575.5 ; v1@3677,2584 v1(3677,2608) ; v1@3677,2599 3669.11,2576.33 v1@3677,2599 ; v1@3677,2599 3684.89,2576.33 v1@3677,2599 ; v1@3677,2599 3673.01,2575.33 v1@3677,2599 ; v1@3677,2599 3680.99,2575.33 v1@3677,2599 ; v1(3677,2608) v1@3679,2608 ; v1(3677,2608) v1@3701,2608 ; v1(3677,2608) v1@3700.45,2600.54 ; v1(3677,2608) v1@3700.45,2615.46 ; v1(3677,2608) v1@3700.86,2604.32 ; v1(3677,2608) v1@3700.86,2611.68 ; v1(3677,2608) v1@3701,2608 ; v1@3679,2608 v1(3703,2608) v1@3679,2608 ; v1@3701,2608 3678.33,2615.89 v1@3701,2608 ; v1@3701,2608 3678.33,2600.11 v1@3701,2608 ; v1@3701,2608 3677.33,2611.99 v1@3701,2608 ; v1@3701,2608 3677.33,2604.01 v1@3701,2608
  Bottom w5: v1@3671,2579.5 3691.33,2600.36 ; v1@3671.72,2580.33 3695.7,2598.81 ; v1@3672.11,2580.68 3698.19,2598.19 ; v1@3672.6,2581.07 3700.04,2596.31 ; v1@3677,2577 v1@3703,2603 ; v1@3682.71,2570.14 3700.04,2596.31 ; v1@3683.1,2570.64 3698.19,2598.19 ; v1@3683.43,2571.13 3695.7,2598.81 ; v1@3683.95,2572.18 3691.33,2600.36 ; v1@3695.53,2575.32 v1@3696.79,2602.7 ; v1@3695.57,2606.96 v1@3703,2581 ; v1@3695.68,2609.65 3703,2625 ; v1@3696,2578.68 v1@3709.21,2602.7 ; v1@3696.61,2611.92 3683.72,2583.72 ; v1@3708.27,2602.66 3683.72,2583.72 ; v1@3710,2578.68 v1@3696.79,2602.7 ; v1@3710.32,2609.65 3703,2625 ; v1@3710.47,2575.32 v1@3709.21,2602.7 ; v1@3710.43,2606.96 v1@3703,2581 ; v1(3677,2575) 3698.19,2598.19 ; v1(3677,2575) 3700.04,2596.31 ; v1(3677,2575) 3691.33,2600.36 ; v1(3677,2575) 3695.7,2598.81 ; 3683.72,2583.72 v1(3703,2608) ; v1@3696.79,2602.7 v1(3703,2576) ; v1(3703,2576) v1@3703,2603 ; v1(3703,2576) v1@3709.21,2602.7 ; v1(3703,2576) v1@3703,2603 ; v1@3703,2581 v1(3703,2608) ; v1@3703,2603 v1(3703,2608) ; v1@3703,2603 3695.57,2577.04 v1@3703,2603 ; v1@3703,2603 3710.43,2577.04 v1@3703,2603 ; v1(3703,2608) 3703,2625
  Bottom w20: v2(2575,2410) 2575,2433.7 ; 2583,2527 2586.9,2523.1 C97.1@2586.9,2488.7 ; 2575,2433.7 2586.9,2445.6 ; 2575,2433.7 C103.1@2586.9,2458.7 ; 2586.9,2445.6 C103.1@2586.9,2458.7 ; 2586.9,2445.6 C103.1@2586.9,2458.7 ; 2586.9,2445.6 C103.1@2586.9,2458.7 ; C103.1@2586.9,2458.7 C97.1@2586.9,2488.7 ; C103.1@2586.9,2458.7 C97.1@2586.9,2488.7
  Bottom w40: 2583,2527 2583,2972.5 3035.5,3425 3330,3425 3570,3185 3655,3185 3700,3140 3700,2629 ; 3703,2625 3703,2626 ; v1(3677,2608) 3703,2626 ; v1(3677,2608) v1(3703,2608) ; v1(3677,2608) v1(3703,2608) ; v1(3677,2608) 3700,2629 ; v1(3677,2608) v1(3703,2608) ; v1(3677,2608) 3700,2629 ; v1(3677,2608) v1(3703,2608) ; v1(3677,2608) 3700,2629 ; v1(3677,2608) v1(3703,2608) ; v1(3677,2608) 3700,2740.35 ; v1(3677,2608) 3700,2629 ; v1(3677,2608) v1(3703,2608) ; v1(3677,2608) v1(3703,2608) ; v1(3677,2608) v1(3703,2608) ; v1(3677,2608) 3660,2665 3700,2740.35 ; v1@3679,2608 3700,2629 ; v1@3679,2608 3677,2606 v1(3703,2608) ; v1@3679,2608 v1(3703,2608) ; v1@3679,2608 v1(3703,2608) ; 3700,2629 3703,2626 ; 3700,2629 v1(3703,2608) ; 3700,2629 v1(3703,2608) ; 3700,2629 v1(3703,2608) ; 3700,2740.35 v1(3703,2608) ; v1(3703,2608) 3703,2626
SOC_COMP_1-CPU-RT0: C37.1 C38.1 U1.C14 | length 1367.8
  Top w4.5: U1.C14@2768.41,2198.46 2772.05,2216.2 ; U1.C14@2772.05,2198.1 2772.05,2216.2 ; U1.C14@2775.68,2198.46 2772.05,2216.2 ; C38.1@3560.57,2534.81 3571,2513.11 ; C37.1@3563.36,2490.28 3571,2512.5 ; C38.1@3564.81,2536.38 3571,2513.11 ; C37.1@3565.04,2493.96 3550.92,2470.92 ; C37.1@3567.76,2489.22 3571,2512.5 ; C37.1@3568.68,2491.28 3550.92,2470.92 ; C38.1@3571.25,2537.19 3571,2513.11 ; C37.1@3573.03,2486.46 3550.92,2470.92 ; C37.1@3574.24,2489.22 3571,2512.5 ; C37.1@3575.31,2482.56 3550.92,2470.92 ; C38.1@3575.74,2536.72 3571,2513.11 ; C37.1@3578.64,2490.28 3571,2512.5 ; 2772.05,2216.2 2818.26,2262.42 3030.42,2262.42 3238,2470 3550,2470 3571,2491 C37.1@3571,2489 ; 3550.92,2470.92 C37.1@3571,2489 ; C37.1@3571,2489 3571,2534 C38.1@3568,2537 3571,2513.11
SOC_FB_1-CPU-RT0: C38.2 R21.2 R22.2 R24.1 R26.2 U1.A13 | length 2863.4
  Top w4: R26.2@3533,2573 C38.2@3568,2573 ; R26.2@3533.36,2569.02 3555,2573 ; R26.2@3533.36,2576.98 3555,2573 ; R26.2@3534.45,2565.13 3555,2573 ; R26.2@3534.45,2580.87 3555,2573 ; C38.2@3566.55,2565.13 3546,2573 ; C38.2@3566.55,2580.87 3546,2573 ; C38.2@3567.64,2569.02 3546,2573 ; C38.2@3567.64,2576.98 3546,2573 ; C38.2@3568.36,2569.02 3590,2573 ; C38.2@3568.36,2576.98 3590,2573 ; C38.2@3569.45,2565.13 3590,2573 ; C38.2@3569.45,2580.87 3590,2573 ; R22.2@3601.55,2565.13 3581,2573 ; R22.2@3601.55,2580.87 3581,2573 ; R22.2@3602.64,2569.02 3581,2573 ; R22.2@3602.64,2576.98 3581,2573 ; 3546,2573 C38.2@3568,2573 ; C38.2@3568,2573 R22.2@3603,2573 3581,2573
  Top w4.5: U1.A13@2787.81,2255.2 2803.86,2266.1 U1.A13@2792.96,2250.05 ; U1.A13@2790.14,2252.38 2809.84,2272.08 3025.08,2272.08 3233,2480 3427,2480 3519,2572 ; R26.2@3530.34,2580.28 3519,2572 ; R26.2@3531.4,2565.42 3519,2572 ; R26.2@3532.39,2576.19 3519,2572 ; R26.2@3532.85,2569.75 3519,2572 ; R22.2@3603.09,2569.75 3626.53,2572 ; R22.2@3603.36,2576.23 3626.53,2572 ; R22.2@3603.95,2565.31 3626.53,2572 ; R22.2@3604.6,2580.58 3626.53,2572 ; R24.1@3628.49,2608.09 3638,2586.39 ; R21.2@3630.36,2574.28 3638,2596.5 ; R24.1@3632.79,2609.5 3638,2586.39 ; R21.2@3634.76,2573.22 3638,2596.5 ; R21.2@3635.31,2580.27 3614.41,2568.41 ; R21.2@3635.55,2565.65 3613.64,2577.04 ; R21.2@3636.03,2580.5 3614.55,2570.85 ; R21.2@3636.34,2565.43 3614.11,2574.27 ; R21.2@3636.4,2580.58 3614.47,2572 ; R21.2@3636.57,2580.62 3614.41,2572.51 ; R21.2@3636.88,2565.33 3614.41,2572.51 ; R21.2@3637.05,2565.31 3614.47,2572 ; R21.2@3637.16,2576.14 3614.41,2568.41 ; R21.2@3637.15,2580.7 3614.11,2574.27 ; R21.2@3637.26,2569.84 3613.64,2577.04 ; R21.2@3637.43,2565.27 3614.55,2570.85 ; R21.2@3637.48,2576.21 3614.55,2570.85 ; R21.2@3637.61,2569.77 3614.11,2574.27 ; R21.2@3637.64,2576.23 3614.47,2572 ; R21.2@3637.71,2576.24 3614.41,2572.51 ; R21.2@3637.84,2569.75 3614.41,2572.51 ; R21.2@3637.91,2569.75 3614.47,2572 ; R21.2@3637.95,2576.25 3614.11,2574.27 ; R21.2@3638.07,2569.75 3614.55,2570.85 ; R21.2@3638.05,2580.75 3613.64,2577.04 ; R21.2@3638.23,2565.25 3614.41,2568.41 ; R21.2@3638.32,2576.23 3613.64,2577.04 ; R21.2@3638.4,2569.77 3614.41,2568.41 ; R24.1@3639.25,2610.05 3638,2586.39 ; R21.2@3641.24,2573.22 3638,2596.5 ; R24.1@3643.73,2609.38 3638,2586.39 ; R21.2@3645.64,2574.28 3638,2596.5 ; 3519,2572 3533,2572 R26.2@3533,2573 3519,2572 ; 3613.64,2577.04 R21.2@3638,2573 ; 3614.11,2574.27 R21.2@3638,2573 ; 3614.41,2568.41 R21.2@3638,2573 ; 3614.41,2572.51 R21.2@3638,2573 ; 3614.47,2572 R21.2@3638,2573 ; 3614.55,2570.85 R21.2@3638,2573 ; 3626.53,2572 R22.2@3603,2573 3602,2573 3603,2572 3638,2572 R21.2@3638,2573 ; 3626.53,2572 R21.2@3636.04,2565.5 ; 3626.53,2572 R21.2@3634.77,2580.04 ; 3626.53,2572 R21.2@3637.82,2569.75 ; 3626.53,2572 R21.2@3637.26,2576.17 ; 3626.53,2572 R21.2@3638,2573 ; 3626.53,2572 R21.2@3636.04,2565.5 ; 3626.53,2572 R21.2@3634.77,2580.04 ; 3626.53,2572 R21.2@3637.82,2569.75 ; 3626.53,2572 R21.2@3637.26,2576.17 ; 3626.53,2572 R21.2@3638,2573 ; 3626.53,2572 R21.2@3636.04,2565.5 ; 3626.53,2572 R21.2@3634.77,2580.04 ; 3626.53,2572 R21.2@3637.82,2569.75 ; 3626.53,2572 R21.2@3637.26,2576.17 ; 3626.53,2572 R21.2@3638,2573 ; 3626.53,2572 R21.2@3636.04,2565.5 ; 3626.53,2572 R21.2@3634.77,2580.04 ; 3626.53,2572 R21.2@3637.82,2569.75 ; 3626.53,2572 R21.2@3637.26,2576.17 ; 3626.53,2572 R21.2@3638,2573 ; 3626.53,2572 R21.2@3636.04,2565.5 ; 3626.53,2572 R21.2@3634.77,2580.04 ; 3626.53,2572 R21.2@3637.82,2569.75 ; 3626.53,2572 R21.2@3637.26,2576.17 ; 3626.53,2572 R21.2@3638,2573 ; R21.2@3638,2573 3638,2610 R24.1@3636,2610 3638,2586.39
SPI_CLK: R125.2 R127.2 SR1.2 U18.6 | length 4075.7
  Top w4.5: v1@3321.95,3273.88 3347.29,3290.54 ; v1@3324.7,3270.3 3347.29,3290.54 ; v1@3329.53,3265.96 3347.29,3290.54 ; v1@3333.38,3263.59 3347.29,3290.54 ; R125.2@3394.25,3600.21 R127.2@3397.44,3575.32 ; R125.2@3394.3,3599.12 R127.2@3402,3566 ; R125.2@3394.29,3599.25 R127.2@3400.46,3575.64 ; R127.2@3394.42,3564.4 3403,3542.45 ; R127.2@3394.42,3567.6 3403,3589.52 ; R125.2@3394.42,3598.4 3403,3576.48 ; R125.2@3394.51,3598 3404.24,3576.56 ; R125.2@3394.76,3597.23 3406.89,3576.39 ; R127.2@3398.77,3565.64 3403,3542.45 ; R127.2@3398.77,3566.36 3403,3589.52 ; R125.2@3398.77,3599.64 3403,3576.48 ; R125.2@3398.75,3599.84 R127.2@3402,3566 ; R125.2@3398.75,3599.99 R127.2@3400.46,3575.64 ; R125.2@3398.77,3600.38 R127.2@3397.44,3575.32 ; R125.2@3398.79,3599.47 3404.24,3576.56 ; R125.2@3398.87,3599.13 3406.89,3576.39 ; R125.2@3405.15,3599.2 R127.2@3397.44,3575.32 ; R125.2@3405.22,3599.58 R127.2@3400.46,3575.64 ; R125.2@3405.22,3600.44 3406.89,3576.39 ; R127.2@3405.25,3565.91 3403,3542.45 ; R127.2@3405.25,3566.09 3403,3589.52 ; R125.2@3405.25,3599.84 R127.2@3402,3566 ; R125.2@3405.25,3599.91 3403,3576.48 ; R125.2@3405.25,3600.09 3404.24,3576.56 ; R125.2@3409.31,3597.43 R127.2@3397.44,3575.32 ; R125.2@3409.56,3598.29 R127.2@3400.46,3575.64 ; R127.2@3409.69,3565.05 3403,3542.45 ; R127.2@3409.69,3566.95 3403,3589.52 ; R125.2@3409.69,3599.05 3403,3576.48 ; R125.2@3409.7,3599.12 R127.2@3402,3566 ; R125.2@3409.73,3599.46 3404.24,3576.56 ; R125.2@3409.74,3600.33 3406.89,3576.39 ; 3347.29,3290.54 v1(3327,3268) 3327,3270.25 3403,3346.25 R127.2@3403,3566 ; R125.2@3395.1,3596.47 3403,3589.52 ; R125.2@3395.1,3596.47 3403,3589.52 ; R125.2@3395.1,3596.47 3403,3589.52 ; R125.2@3395.1,3596.47 3403,3589.52 ; R125.2@3395.1,3596.47 3403,3589.52 ; R127.2@3397.44,3575.32 R125.2@3402,3600 ; R125.2@3398.85,3599.2 3403,3589.52 ; R125.2@3398.85,3599.2 3403,3589.52 ; R125.2@3398.85,3599.2 3403,3589.52 ; R125.2@3398.85,3599.2 3403,3589.52 ; R125.2@3398.85,3599.2 3403,3589.52 ; R127.2@3400.46,3575.64 R125.2@3402,3600 ; R127.2@3402,3566 R127.2@3403,3566 ; R127.2@3402,3566 3403,3589.52 ; R127.2@3402,3566 3403,3542.45 ; R127.2@3402,3566 R125.2@3402,3600 ; R125.2@3402,3600 3403,3600 R127.2@3403,3566 ; R125.2@3402,3600 3403,3576.48 ; R125.2@3402,3600 3403,3589.52 ; R125.2@3402,3600 3406.89,3576.39 ; R125.2@3402,3600 3403,3589.52 ; R125.2@3402,3600 3403,3589.52 ; R125.2@3402,3600 3404.24,3576.56 ; R125.2@3402,3600 3403,3589.52 ; R125.2@3402,3600 3403,3589.52 ; 3403,3589.52 R125.2@3409.44,3597.84 ; 3403,3589.52 R125.2@3405.24,3599.81 ; 3403,3589.52 R125.2@3409.44,3597.84 ; 3403,3589.52 R125.2@3405.24,3599.81 ; 3403,3589.52 R125.2@3409.44,3597.84 ; 3403,3589.52 R125.2@3405.24,3599.81 ; 3403,3589.52 R125.2@3409.44,3597.84 ; 3403,3589.52 R125.2@3405.24,3599.81 ; 3403,3589.52 R125.2@3409.44,3597.84 ; 3403,3589.52 R125.2@3405.24,3599.81
  Top w5: U18.6@3217.98,4029.34 3245.22,4045.22 ; U18.6@3220.86,4025.2 3245.22,4045.22 ; U18.6@3225,4009.8 3225,4025 3273.5,4073.5 3318.5,4073.5 3400,3992 3400,3603 3403,3600 R125.2@3402,3600 3400,3625.27 ; U18.6@3225,4021.02 3245.22,4045.22 ; U18.6@3229.85,4017.69 3245.22,4045.22 ; U18.6@3234.43,4015.59 3245.22,4045.22 ; R125.2@3394.52,3600.52 3400,3625.27 ; R125.2@3409.31,3601.69 3400,3625.27
  Inner Layer 3 w5: v1(2960,2496) 2974,2496 ; v1@2962.01,2488.77 2974,2496 ; v1@2962.01,2503.23 2974,2496 ; v1@3321.11,3272.64 3304.39,3245.39 v1@3331.64,3262.11 ; v1(3327,3268) 3299,3240 3184,3240 3110,3166 3110,2632 2974,2496
  Bottom w5: SR1.2@2787.42,2405.94 2812.61,2420.61 SR1.2@2797.94,2395.42 ; SR1.2@2792,2400 2830,2438 2924,2438 2960,2474 ; v1@2952.61,2494.72 2960,2474 ; v1(2960,2496) 2960,2474 ; v1@2967.39,2494.72 2960,2474
SPI_CS0: R170.1 U1.C7 U18.1 | length 2403.6
  Top w4: R170.1@3110.71,3658.29 3125,3680.22 ; U18.1@3113.9,3696.42 3125,3673.59 ; R170.1@3114.24,3656.36 3125,3680.22 ; U18.1@3117.69,3697.9 3125,3673.59 ; U18.1@3121.62,3698.75 3125,3673.59 ; R170.1@3121.92,3654.23 3125,3680.22 ; U18.1@3125,3698.98 3125,3673.59 ; U18.1@3125,3710.2 3125,3661.5 3124.5,3661.5 R170.1@3118,3655 3125,3680.22 ; R170.1@3125.94,3654.06 3125,3680.22 ; U18.1@3128.38,3698.75 3125,3673.59 ; U18.1@3132.31,3697.9 3125,3673.59 ; U18.1@3136.1,3696.42 3125,3673.59
  Top w4.5: v1@3106.45,3294.76 3116,3318.68 ; R170.1@3110.27,3654.39 3116,3631.29 ; v1@3110.78,3293.46 3116,3318.68 ; R170.1@3114.75,3655.05 3116,3631.29 ; v1@3117.25,3292.95 3116,3318.68 ; R170.1@3121.21,3654.51 3116,3631.29 ; v1@3121.73,3293.57 3116,3318.68 ; R170.1@3125.51,3653.1 3116,3631.29 ; 3116,3318.68 v1(3114,3293) 3116,3295 3116,3654 R170.1@3118,3655 3116,3631.29
  Top w8: U1.C7@2645.38,2324.76 2645.38,2308.32 U1.C7@2645.38,2324.76 ; U1.C7@2645.38,2324.76 v2(2645.6,2308.1) U1.C7@2645.38,2324.76
  Top w10: v2@2645.38,2308.32 v2(2645.6,2308.1)
  Inner Layer 3 w4.5: v2(2645.6,2308.1) 2659.53,2308.1 ; v2@2646.79,2302.47 2659.53,2308.1 ; v2@2646.79,2313.73 2659.53,2308.1 ; v1@3112.65,3285.37 3091.73,3293 ; v1@3112.65,3300.63 3091.73,3293 ; v1@3113.76,3289.76 3091.73,3293 ; v1@3113.76,3296.24 3091.73,3293 ; 2659.53,2308.1 2677.43,2326 2709.87,2326 2756,2372.13 2756,2401.28 3020,2665.28 3020,3221.27 3091.73,3293 ; 3091.73,3293 v1(3114,3293) 3091.73,3293
SPI_CS1_1-CPU-RT0: R831.1 U1.C9 | length 541.2
  Top w5: U1.C9@2678.18,2288.24 2681.6,2270.6 ; U1.C9@2681.57,2288.57 2681.6,2270.6 ; U1.C9@2684.96,2288.25 2681.6,2270.6 ; v2@2695.53,2249.04 2681.6,2270.6 ; v2(2699.8,2252.5) 2681.6,2270.6 ; v2@2703.24,2256.79 2681.6,2270.6
  Bottom w5: v2@2695.72,2256.19 2717.47,2276.17 ; v2@2704.49,2249.63 2717.47,2276.17 ; R831.1@2911.38,2316.08 2887.5,2323.5 ; R831.1@2911.38,2330.92 2887.5,2323.5 ; R831.1@2913.5,2323.5 R831.1@2912.5,2323.5 ; 2717.47,2276.17 v2(2699.8,2252.5) 2699.8,2258.5 2764.8,2323.5 R831.1@2912.5,2323.5 ; 2887.5,2323.5 R831.1@2912.5,2323.5
SPI_HOLD: R142.2 R823.1 R824.1 U1.B8 | length 3254.4
  Top w4.5: U1.B8@2677.93,2325.14 2681.57,2342.66 ; U1.B8@2685.21,2325.14 2681.57,2342.66 ; v1@2874.82,2462.34 2850.5,2470 ; v1@2874.82,2477.66 2850.5,2470 ; v1@2875.79,2466.76 2850.5,2470 ; v1@2875.79,2473.24 2850.5,2470 ; v1(2876,2470) 2814.97,2470 2706.97,2362 2700.91,2362 2681.57,2342.66 ; R823.1@2955.38,3951.27 2982.44,3953 ; R823.1@2955.47,3955.79 2982.44,3953 ; R823.1@2956.91,3962.12 2982.44,3953 ; R823.1@2958.78,3966.24 2982.44,3953 ; R824.1@3017.36,3956.72 3025,3934.5 ; R142.2@3020.26,3920.29 3025,3943.8 ; R824.1@3021.76,3957.78 3025,3934.5 ; R824.1@3022.28,3965.26 3000.66,3953 ; R142.2@3023.69,3913.56 3048.18,3901.82 ; R824.1@3024.14,3961.13 3000.66,3953 ; R142.2@3024.76,3919.81 3025,3943.8 ; R824.1@3025.36,3950.26 3000.66,3953 ; R824.1@3025.44,3954.78 3000.66,3953 ; R142.2@3025.97,3917.46 3048.18,3901.82 ; R824.1@3028.24,3957.78 3025,3934.5 ; R142.2@3030.32,3922.28 3048.18,3901.82 ; R142.2@3031.19,3920.62 3025,3943.8 ; R824.1@3032.64,3956.72 3025,3934.5 ; R142.2@3033.96,3924.96 3048.18,3901.82 ; R142.2@3035.43,3922.2 3025,3943.8 ; v1@3068.34,3227.18 3076,3251.5 ; v1@3072.76,3226.21 3076,3251.5 ; v1(3076,3226) 3076,3344 3054,3366 3054,3896 3040,3910 ; v1@3079.24,3226.21 3076,3251.5 ; v1@3083.66,3227.18 3076,3251.5 ; 2681.57,2342.66 U1.B8@2681.57,2324.76 2681.57,2342.66 ; 2982.44,3953 R823.1@2956,3959 2956,3960 2963,3953 3025,3953 R824.1@3025,3958 ; 3000.66,3953 R824.1@3025,3958 ; 3025,3943.8 R142.2@3028,3920 ; R824.1@3025,3958 3025,3922 3029.49,3917.51 R142.2@3027,3920 ; R142.2@3027,3920 R142.2@3028,3920 ; R142.2@3027,3920 3037,3910 3040,3910 ; R142.2@3028,3920 3040,3910 ; R142.2@3028,3920 3048.18,3901.82 ; R142.2@3028,3920 3040,3910 ; 3040,3910 3034.28,3924.54 3040,3910 ; 3040,3910 3024.67,3913 3040,3910 ; 3040,3910 3030.33,3922.27 3040,3910 ; 3040,3910 3026.19,3917.3 3040,3910
  Inner Layer 3 w4.5: v1@2870.01,2474.91 2893.69,2497.69 ; v1@2873.35,2471.88 2893.69,2497.69 ; v1@2878.82,2468.39 2893.69,2497.69 ; v1@2882.98,2466.63 2893.69,2497.69 ; v1@3069.87,3230.74 3054.45,3204.45 ; v1@3073.58,3228.17 3054.45,3204.45 ; v1(3076,3226) 3050,3200 3050,2654 2876,2480 v1(2876,2470) 2893.69,2497.69 ; v1@3078.17,3223.58 3054.45,3204.45 ; v1@3080.74,3219.87 3054.45,3204.45
SPI_MISO: U1.C8 U18.2 | length 2015.3
  Top w4: U18.2@3174.44,3721.06 3175,3720.5 U18.2@3175,3710.2
  Top w4.5: v1(3140,3305) 3128,3317 3128,3633 3170,3675 ; U18.2@3163.87,3698.71 3170,3675 ; U18.2@3168.38,3699.44 3170,3675 ; U18.2@3174.44,3721.06 3170,3716.61 3170,3675 ; U18.2@3175,3698.98 3170,3675 ; U18.2@3181.25,3696.75 3170,3675 ; U18.2@3185.1,3694.28 3170,3675
  Top w10: U1.C8@2663.48,2306.67 v2@2679.97,2306.67 ; U1.C8@2663.48,2306.67 v2@2679.97,2306.67 ; U1.C8@2663.48,2306.67 v2(2680.2,2306.9) ; U1.C8@2663.48,2306.67 v2(2680.2,2306.9) ; v2@2679.97,2306.67 v2(2680.2,2306.9)
  Inner Layer 3 w4.5: v2(2680.2,2306.9) 2689.3,2316 2713.31,2316 2768,2370.69 2768,2399.84 3030,2661.84 3030,3217.83 3080.17,3268 3113.4,3268 3140,3294.6 v1(3140,3305) 3124.25,3278.85 ; v1@3132.91,3308.12 3124.25,3278.85 ; v1@3137.13,3306.53 3124.25,3278.85 ; v1@3142.69,3303.18 3124.25,3278.85 ; v1@3146.08,3300.19 3124.25,3278.85
SPI_MOSI: R133.2 R135.2 U1.A8 U18.5 | length 4317.9
  Top w4: R135.2@3335.13,3566.45 3343,3587 ; R133.2@3335.13,3598.55 3343,3578 ; R135.2@3339.02,3565.36 3343,3587 ; R133.2@3339.02,3599.64 3343,3578 ; R135.2@3346.98,3565.36 3343,3587 ; R133.2@3346.98,3599.64 3343,3578 ; R135.2@3350.87,3566.45 3343,3587 ; R133.2@3350.87,3598.55 3343,3578 ; 3343,3578 R133.2@3343,3600 3343,3568.5 R135.2@3343,3565 3343,3587
  Top w4.5: U1.A8@2697.52,2345.82 2707.87,2351.06 ; U1.A8@2702.63,2340.71 2707.87,2351.06 ; v1@2895.75,2474.58 2884,2452 ; v1@2899.56,2472.15 2884,2452 ; v1(2902,2470) 2884,2452 ; v1@2904.15,2467.56 2884,2452 ; v1@2906.58,2463.75 2884,2452 ; v1@3250.98,3291.63 3279.23,3304.23 ; v1@3253.12,3287.65 3279.23,3304.23 ; v1@3257.15,3282.56 3279.23,3304.23 ; v1@3260.54,3279.58 3279.23,3304.23 ; U18.5@3264.11,3996.28 3275,3971.7 ; U18.5@3268.41,3997.76 3275,3971.7 ; U18.5@3275,3998.58 3275,3971.7 ; U18.5@3275,4009.8 3275,3971 3341,3905 3341,3601 3343,3599 R135.2@3343,3568.5 ; U18.5@3281.59,3997.76 3275,3971.7 ; U18.5@3285.89,3996.28 3275,3971.7 ; R133.2@3335.25,3600.16 3338.63,3575.8 ; R133.2@3335.27,3600.62 3341,3623.71 ; R135.2@3335.31,3564.05 3342,3541.46 ; R133.2@3335.28,3599.28 3341.31,3576.33 ; R135.2@3335.36,3566.28 3343,3588.5 ; R133.2@3335.44,3598.27 R135.2@3345.11,3573.38 ; R133.2@3335.68,3597.44 R135.2@3348.28,3573.16 ; R135.2@3339.75,3564.91 3342,3541.46 ; R135.2@3339.76,3565.22 3343,3588.5 ; R133.2@3339.75,3599.95 3341,3623.71 ; R133.2@3339.75,3600.01 3341.31,3576.33 ; R133.2@3339.77,3600.36 3338.63,3575.8 ; R133.2@3339.85,3599.18 R135.2@3348.28,3573.16 ; R133.2@3346.15,3599.21 3338.63,3575.8 ; R133.2@3346.22,3600.44 R135.2@3348.28,3573.16 ; R133.2@3346.21,3600.49 3341,3623.71 ; R135.2@3346.23,3564.64 3342,3541.46 ; R135.2@3346.24,3565.22 3343,3588.5 ; R133.2@3346.25,3600.06 R135.2@3345.11,3573.38 ; R133.2@3350.31,3597.44 3338.63,3575.8 ; R133.2@3350.51,3601.9 3341,3623.71 ; R133.2@3350.54,3598.19 3341.31,3576.33 ; R135.2@3350.58,3563.4 3342,3541.46 ; R135.2@3350.64,3566.28 3343,3588.5 ; R133.2@3350.73,3599.48 R135.2@3345.11,3573.38 ; R133.2@3350.74,3600.4 R135.2@3348.28,3573.16 ; 2707.87,2351.06 2709.46,2351.06 2810.39,2452 2884,2452 ; 2707.87,2351.06 U1.A8@2699.67,2342.86 2707.87,2351.06 ; 3279.23,3304.23 v1(3255,3285) 3255,3290 3265,3290 3342,3367 3342,3565 R135.2@3343,3565 ; R133.2@3335.7,3597.39 3343,3588.5 ; R133.2@3335.7,3597.39 3343,3588.5 ; R133.2@3335.7,3597.39 3343,3588.5 ; R133.2@3335.7,3597.39 3343,3588.5 ; R133.2@3335.7,3597.39 3343,3588.5 ; 3338.63,3575.8 R133.2@3343,3600 ; R133.2@3339.78,3599.54 3343,3588.5 ; R133.2@3339.78,3599.54 3343,3588.5 ; R133.2@3339.78,3599.54 3343,3588.5 ; R133.2@3339.78,3599.55 R135.2@3345.11,3573.38 ; R133.2@3339.78,3599.54 3343,3588.5 ; R133.2@3339.78,3599.54 3343,3588.5 ; 3341,3623.71 R133.2@3343,3600 ; 3341.31,3576.33 R133.2@3346.22,3599.55 ; 3341.31,3576.33 R133.2@3343,3600 ; 3342,3541.46 R135.2@3343,3565 ; R135.2@3343,3565 3343,3588.5 ; 3343,3576.5 3350.64,3598.72 3343,3576.5 ; 3343,3576.5 3335.36,3598.72 3343,3576.5 ; 3343,3576.5 3346.24,3599.78 3343,3576.5 ; 3343,3576.5 3339.76,3599.78 3343,3576.5 ; 3343,3576.5 R133.2@3343,3600 ; 3343,3576.5 R133.2@3343,3600 ; 3343,3588.5 R133.2@3350.3,3597.39 ; 3343,3588.5 R133.2@3346.22,3599.54 ; 3343,3588.5 R133.2@3343,3600 ; 3343,3588.5 R133.2@3350.3,3597.39 ; 3343,3588.5 R133.2@3346.22,3599.54 ; 3343,3588.5 R133.2@3343,3600 ; 3343,3588.5 R133.2@3350.3,3597.39 ; 3343,3588.5 R133.2@3346.22,3599.54 ; 3343,3588.5 R133.2@3343,3600 ; 3343,3588.5 R133.2@3350.3,3597.39 ; 3343,3588.5 R133.2@3346.22,3599.54 ; 3343,3588.5 R133.2@3343,3600 ; 3343,3588.5 R133.2@3350.3,3597.39 ; 3343,3588.5 R133.2@3346.22,3599.54 ; R133.2@3343,3600 R135.2@3348.28,3573.16 ; R133.2@3343,3600 R135.2@3345.11,3573.38
  Inner Layer 3 w4.5: v1@2894.29,2470.77 2900,2489 ; v1@2898.75,2469.94 2900,2489 ; v1@2905.19,2470.61 2900,2489 ; v1@2909.38,2472.36 2900,2489 ; v1@3253.82,3277.34 3229.5,3285 ; v1@3253.82,3292.66 3229.5,3285 ; v1@3254.79,3281.76 3229.5,3285 ; v1@3254.79,3288.24 3229.5,3285 ; v1(3255,3285) 3165.6,3285 3062,3181.4 3062,2651 2900,2489 ; 2900,2489 2900,2472 v1(2902,2470) 2900,2489
SPI_WP: D26.2 R136.2 U1.B7 | length 2735.5
  Top w4.5: v2@2657.86,2360.3 U1.B7@2659.84,2343.27 ; v2@2657.92,2359.08 U1.B7@2663.48,2342.86 ; v2@2658.25,2357.89 U1.B7@2667.11,2343.22 ; v2@2668.92,2357.82 U1.B7@2659.84,2343.27 ; v2@2669.26,2358.99 U1.B7@2663.48,2342.86 ; v2@2669.35,2360.22 U1.B7@2667.11,2343.22 ; D26.2@2850.28,4037.52 2873,4032.59 ; D26.2@2851.69,4041.89 2873,4032.59 ; D26.2@2853.89,4045.84 2873,4032.59 ; D26.2@2855.59,4048 2873,4032.59 ; D26.2@2855.59,4050 2873,4032.59 ; D26.2@2857.53,4049.95 2873,4032.59 ; D26.2@2861.18,4052.61 2873,4032.59 ; R136.2@2865.36,3971.28 2873,3993.5 ; D26.2@2865.35,4054.55 2873,4032.59 ; R136.2@2868.8,3963.48 2893.88,3951.94 ; R136.2@2869.76,3970.22 2873,3993.5 ; R136.2@2871.02,3967.42 2893.88,3951.94 ; R136.2@2875.27,3972.33 2893.88,3951.94 ; R136.2@2876.24,3970.22 2873,3993.5 ; R136.2@2878.84,3975.09 2893.88,3951.94 ; R136.2@2880.64,3971.28 2873,3993.5 ; v1(2980,3230) 3042.16,3230 3064,3251.84 3064,3342 3044,3362 3044,3842 3002,3884 2961.82,3884 2874.41,3971.41 2873,3971.41 R136.2@2873,3970 ; v1@2980.21,3226.76 3005.5,3230 ; v1@2980.21,3233.24 3005.5,3230 ; v1@2981.18,3222.34 3005.5,3230 ; v1@2981.18,3237.66 3005.5,3230 ; U1.B7@2659.84,2343.27 v2(2663.6,2360) ; U1.B7@2663.48,2342.86 v2(2663.6,2360) ; v2(2663.6,2360) U1.B7@2667.11,2343.22 ; R136.2@2873,3970 2873,4032.59 ; R136.2@2873,3970 2893.88,3951.94
  Inner Layer 3 w4.5: v2(2663.6,2360) 2703.57,2360 2726,2382.43 2726,2411.6 2990,2675.6 2990,3220 v1(2980,3230) ; v2@2664.3,2354.29 2687.1,2360 v2@2664.3,2365.71
SS1_5-POWER0: C19.1 U3.8 | length 296.8
  Top w4.5: U3.8@6923.63,1563.92 6937,1541.38 ; U3.8@6927.72,1565.89 6937,1541.38 ; C19.1@6929.36,1513.28 6937,1535.5 ; U3.8@6933,1567.28 6937,1541.38 ; U3.8@6933,1579.39 6933,1580.67 6938,1572.5 6937,1571.5 C19.1@6937,1512 ; C19.1@6933.76,1512.22 6937,1535.5 ; U3.8@6938.45,1567.55 6937,1541.38 ; C19.1@6940.24,1512.22 6937,1535.5 ; U3.8@6942.95,1566.91 6937,1541.38 ; C19.1@6944.64,1513.28 6937,1535.5
SS2_5-POWER0: C9.1 U2.8 | length 311
  Top w4.5: C9.1@6441.09,3078.25 6464.53,3076 ; C9.1@6441.36,3071.77 6464.53,3076 ; C9.1@6441.95,3082.69 6464.53,3076 ; C9.1@6442.6,3067.42 6464.53,3076 ; U2.8@6490.6,3090.25 6468.29,3076 ; U2.8@6492.71,3086.22 6468.29,3076 ; U2.8@6494.29,3071.05 6468.29,3076 ; U2.8@6494.28,3081 6468.29,3076 ; U2.8@6494.76,3075.57 6468.29,3076 ; U2.8@6499.5,3076 6440,3076 C9.1@6441,3075 6464.53,3076
SS11_5-POWER0: C315.1 U616.8 | length 279.4
  Top w4.5: U616.8@7010.32,2169.89 7018,2147.64 ; C315.1@7010.36,2124.28 7018,2146.5 ; U616.8@7014.72,2170.95 7018,2147.64 ; C315.1@7014.76,2123.22 7018,2146.5 ; C315.1@7018,2123 U616.8@7018,2190.67 ; U616.8@7018,2171.18 7018,2147.64 ; C315.1@7021.24,2123.22 7018,2146.5 ; U616.8@7021.28,2170.95 7018,2147.64 ; C315.1@7025.64,2124.28 7018,2146.5 ; U616.8@7025.68,2169.89 7018,2147.64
